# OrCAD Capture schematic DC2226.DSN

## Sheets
1 PAGE3: size B; title: WITH JESD204B SERIAL OUTPUTS; rev: 3; note: DEMO CIRCUIT 2226A
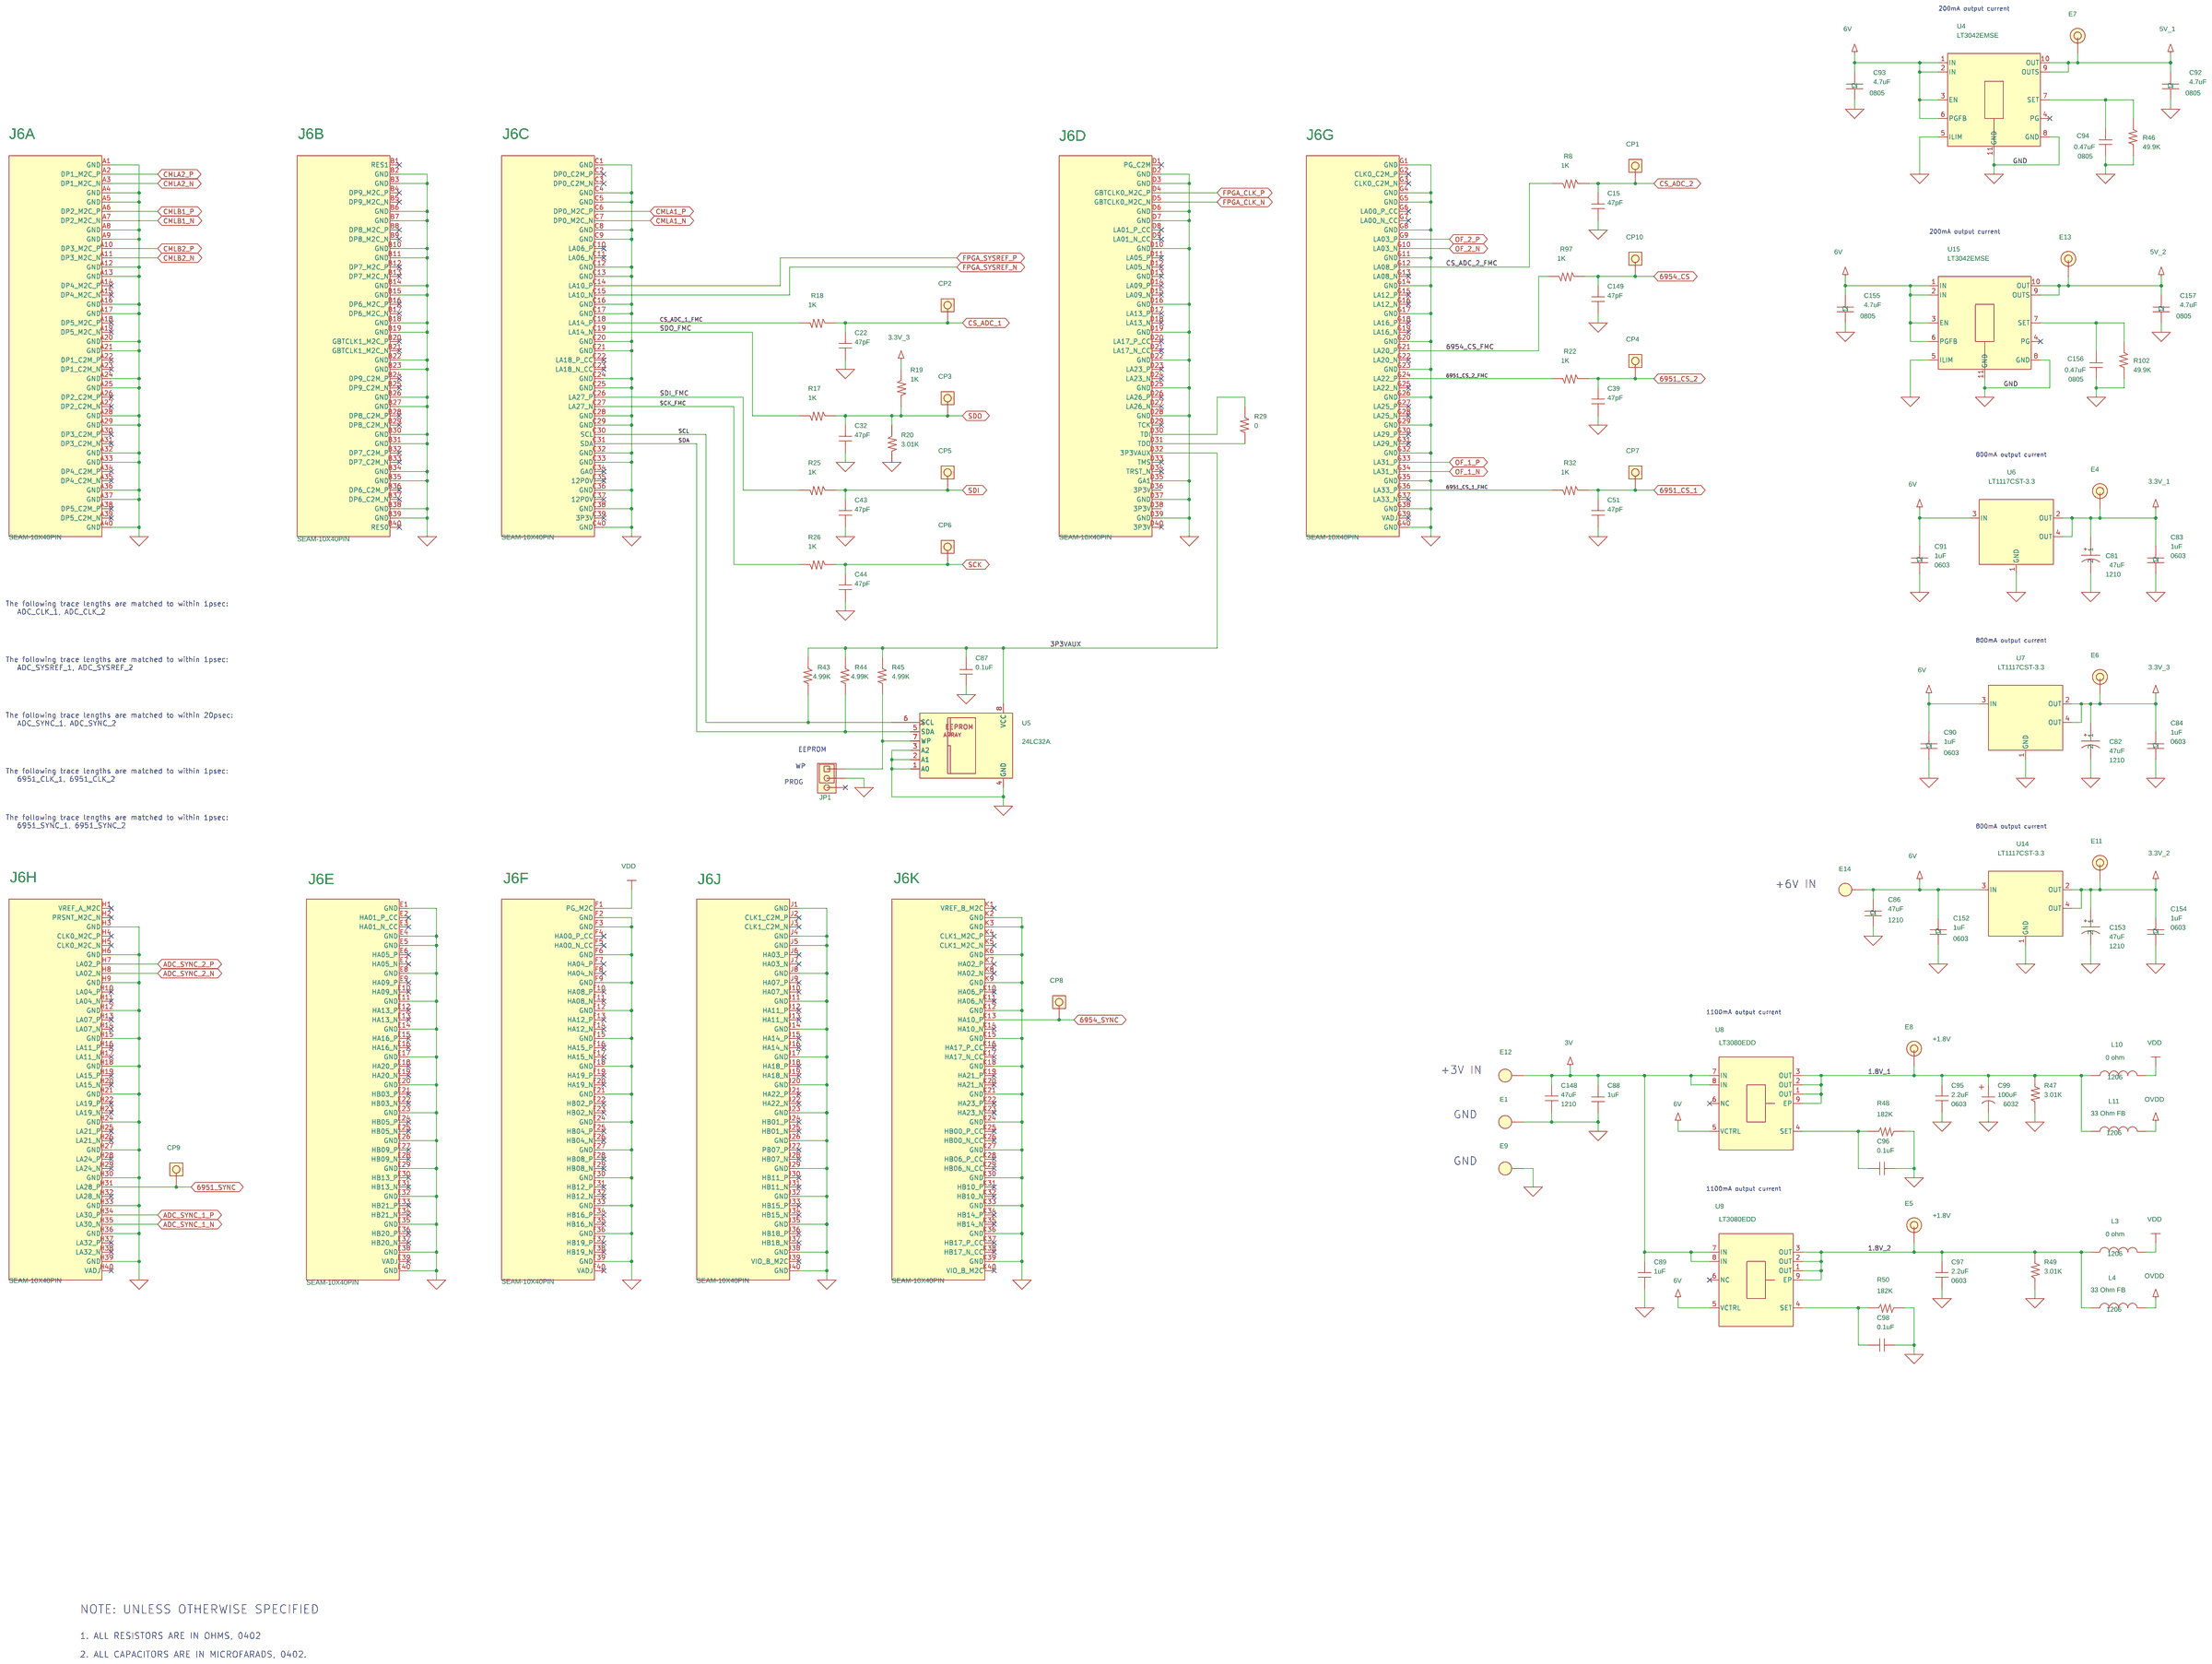
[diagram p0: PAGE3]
2 PAGE2: size B
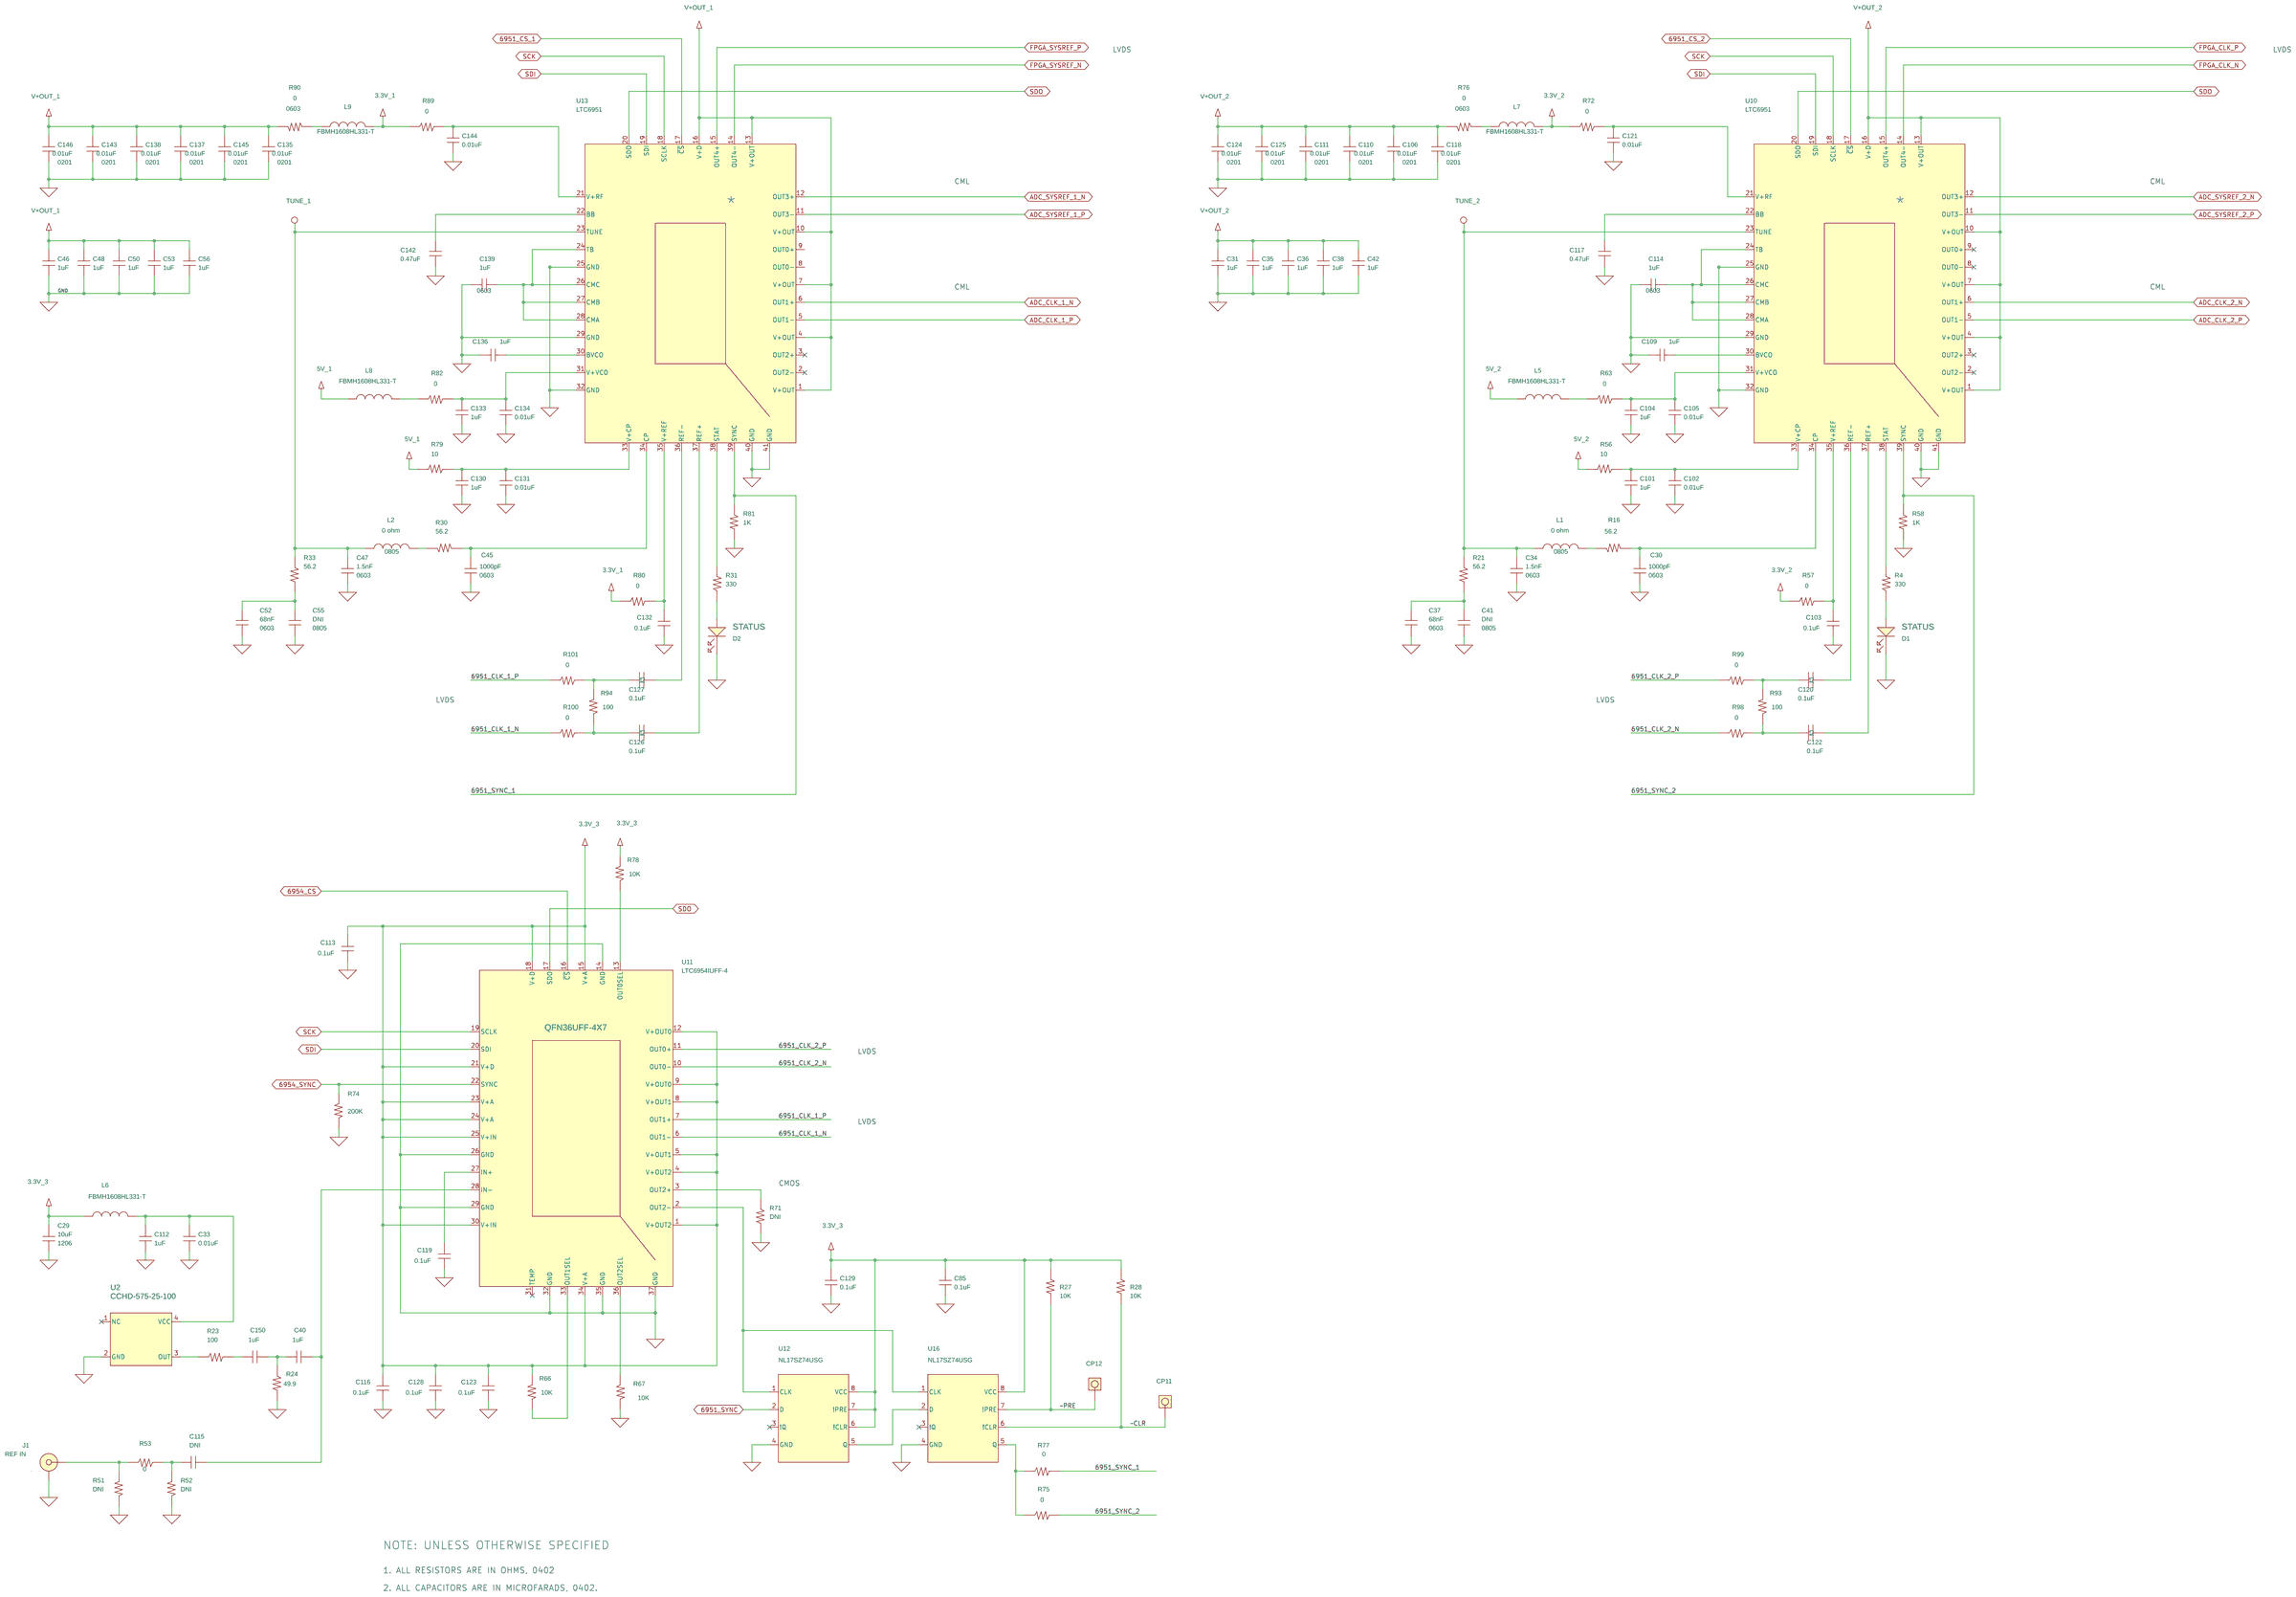
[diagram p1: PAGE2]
3 PAGE1: size B
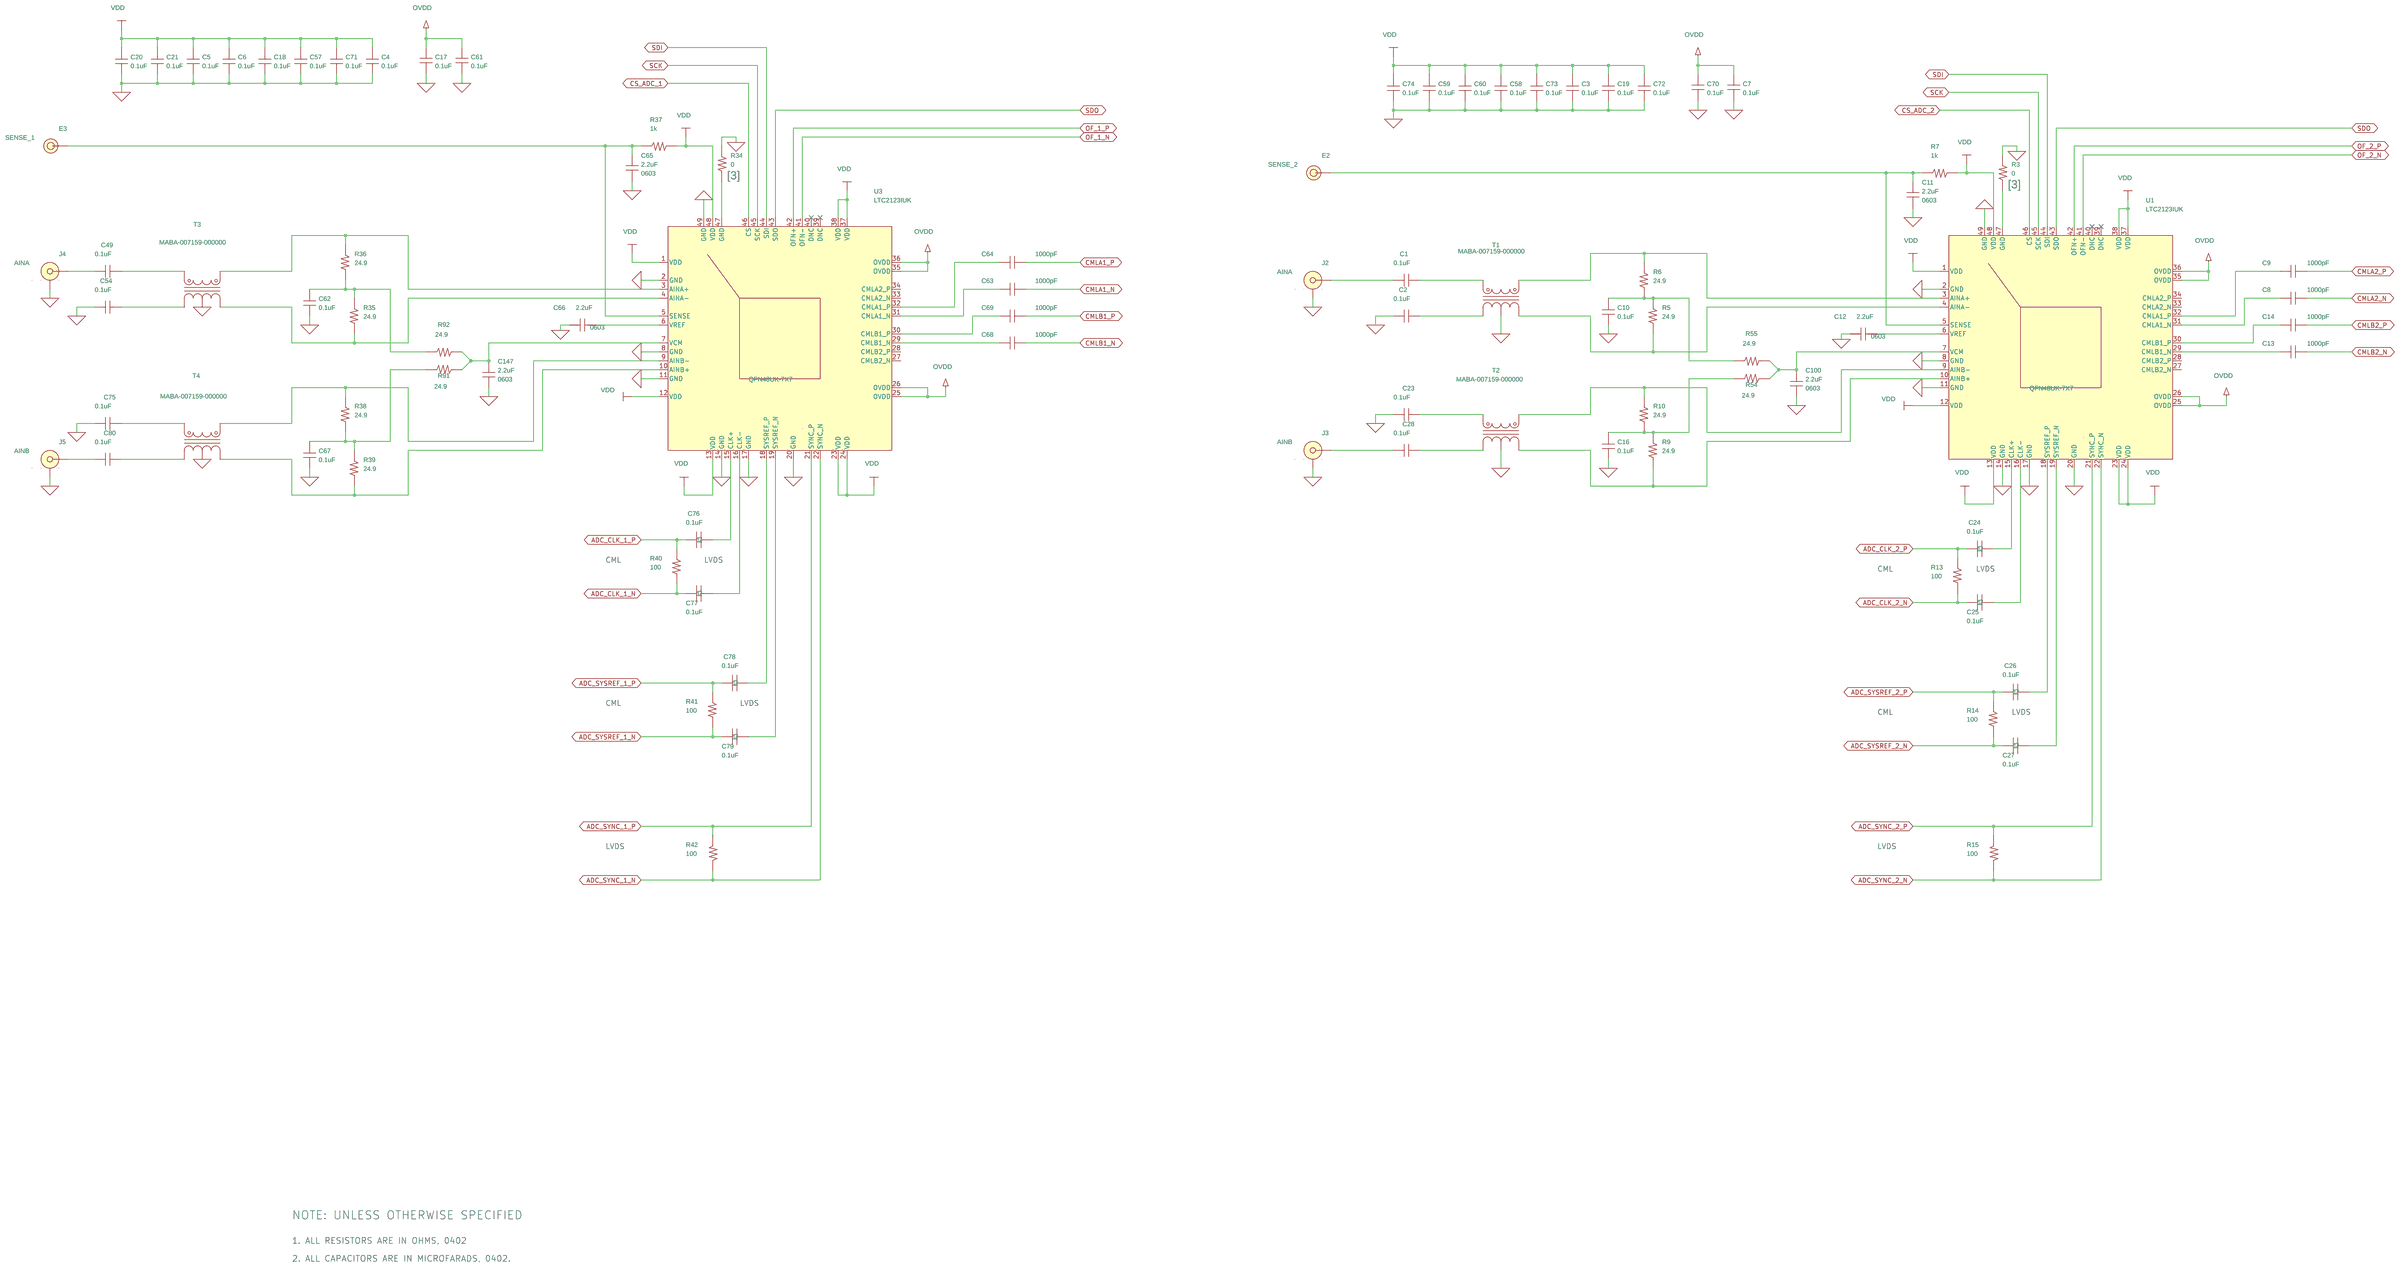
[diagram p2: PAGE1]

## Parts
sheet PAGE1
C1  0.1uF  [0402]
C2  0.1uF  [0402]
C3  0.1uF  [0402]
C4  0.1uF  [0402]
C5  0.1uF  [0402]
C6  0.1uF  [0402]
C7  0.1uF  [0402]
C8  1000pF  [0402]
C9  1000pF  [0402]
C10  0.1uF  [0402]
C11  2.2uF  [0603]
C12  2.2uF  [0603]
C13  1000pF  [0402]
C14  1000pF  [0402]
C16  0.1uF  [0402]
C17  0.1uF  [0402]
C18  0.1uF  [0402]
C19  0.1uF  [0402]
C20  0.1uF  [0402]
C21  0.1uF  [0402]
C23  0.1uF  [0402]
C24  0.1uF  [0402]
C25  0.1uF  [0402]
C26  0.1uF  [0402]
C27  0.1uF  [0402]
C28  0.1uF  [0402]
C49  0.1uF  [0402]
C54  0.1uF  [0402]
C57  0.1uF  [0402]
C58  0.1uF  [0402]
C59  0.1uF  [0402]
C60  0.1uF  [0402]
C61  0.1uF  [0402]
C62  0.1uF  [0402]
C63  1000pF  [0402]
C64  1000pF  [0402]
C65  2.2uF  [0603]
C66  2.2uF  [0603]
C67  0.1uF  [0402]
C68  1000pF  [0402]
C69  1000pF  [0402]
C70  0.1uF  [0402]
C71  0.1uF  [0402]
C72  0.1uF  [0402]
C73  0.1uF  [0402]
C74  0.1uF  [0402]
C75  0.1uF  [0402]
C76  0.1uF  [0402]
C77  0.1uF  [0402]
C78  0.1uF  [0402]
C79  0.1uF  [0402]
C80  0.1uF  [0402]
C100  2.2uF  [0603]
C147  2.2uF  [0603]
E2  MILL-MAX-2308  [MILL-MAX-2308]
E3  MILL-MAX-2308  [MILL-MAX-2308]
J2  CON-SMA-R-6LAYERS  [CON-SMA-R-6LAYERS]
J3  CON-SMA-R-6LAYERS  [CON-SMA-R-6LAYERS]
J4  CON-SMA-R-6LAYERS  [CON-SMA-R-6LAYERS]
J5  CON-SMA-R-6LAYERS  [CON-SMA-R-6LAYERS]
R3  0  [0402]
R5  24.9  [0402]
R6  24.9  [0402]
R7  1k  [0402]
R9  24.9  [0402]
R10  24.9  [0402]
R13  100  [0402]
R14  100  [0402]
R15  100  [0402]
R34  0  [0402]
R35  24.9  [0402]
R36  24.9  [0402]
R37  1k  [0402]
R38  24.9  [0402]
R39  24.9  [0402]
R40  100  [0402]
R41  100  [0402]
R42  100  [0402]
R54  24.9  [0402]
R55  24.9  [0402]
R91  24.9  [0402]
R92  24.9  [0402]
T1  MABA-007159-000000  [TRANS-SM-22-M/A-COM]
T2  MABA-007159-000000  [TRANS-SM-22-M/A-COM]
T3  MABA-007159-000000  [TRANS-SM-22-M/A-COM]
T4  MABA-007159-000000  [TRANS-SM-22-M/A-COM]
U1  LTC2123IUK  [QFN48UK-7X7]
U3  LTC2123IUK  [QFN48UK-7X7]
sheet PAGE2
C29  10uF  [1206]
C30  1000pF  [0603]
C31  1uF  [0402]
C33  0.01uF  [0402]
C34  1.5nF  [0603]
C35  1uF  [0402]
C36  1uF  [0402]
C37  68nF  [0603]
C38  1uF  [0402]
C40  1uF  [0402]
C41  DNI  [0805]
C42  1uF  [0402]
C45  1000pF  [0603]
C46  1uF  [0402]
C47  1.5nF  [0603]
C48  1uF  [0402]
C50  1uF  [0402]
C52  68nF  [0603]
C53  1uF  [0402]
C55  DNI  [0805]
C56  1uF  [0402]
C85  0.1uF  [0402]
C101  1uF  [0402]
C102  0.01uF  [0402]
C103  0.1uF  [0402]
C104  1uF  [0402]
C105  0.01uF  [0402]
C106  0.01uF  [0201]
C109  1uF  [0402]
C110  0.01uF  [0201]
C111  0.01uF  [0201]
C112  1uF  [0402]
C113  0.1uF  [0402]
C114  1uF  [0603]
C115  DNI  [0402]
C116  0.1uF  [0402]
C117  0.47uF  [0402]
C118  0.01uF  [0201]
C119  0.1uF  [0402]
C120  0.1uF  [0402]
C121  0.01uF  [0402]
C122  0.1uF  [0402]
C123  0.1uF  [0402]
C124  0.01uF  [0201]
C125  0.01uF  [0201]
C126  0.1uF  [0402]
C127  0.1uF  [0402]
C128  0.1uF  [0402]
C129  0.1uF  [0402]
C130  1uF  [0402]
C131  0.01uF  [0402]
C132  0.1uF  [0402]
C133  1uF  [0402]
C134  0.01uF  [0402]
C135  0.01uF  [0201]
C136  1uF  [0402]
C137  0.01uF  [0201]
C138  0.01uF  [0201]
C139  1uF  [0603]
C142  0.47uF  [0402]
C143  0.01uF  [0201]
C144  0.01uF  [0402]
C145  0.01uF  [0201]
C146  0.01uF  [0201]
C150  1uF  [0402]
CP11  TESTPAD-SMD/050SQ  [TESTPAD-SMD/050SQ]
CP12  TESTPAD-SMD/050SQ  [TESTPAD-SMD/050SQ]
D1  SML-010VT  [LED-ROHM-SML-010]
D2  SML-010VT  [LED-ROHM-SML-010]
J1  CON-SMA-R-6LAYERS  [AMPHENOL-132134]
L1  0 ohm  [0805]
L2  0 ohm  [0805]
L5  FBMH1608HL331-T  [L-0603LS-1608]
L6  FBMH1608HL331-T  [L-0603LS-1608]
L7  FBMH1608HL331-T  [L-0603LS-1608]
L8  FBMH1608HL331-T  [L-0603LS-1608]
L9  FBMH1608HL331-T  [L-0603LS-1608]
R4  330  [0402]
R16  56.2  [0402]
R21  56.2  [0402]
R23  100  [0402]
R24  49.9  [0402]
R27  10K  [0402]
R28  10K  [0402]
R30  56.2  [0402]
R31  330  [0402]
R33  56.2  [0402]
R51  DNI  [0402]
R52  DNI  [0402]
R53  0  [0402]
R56  10  [0402]
R57  0  [0402]
R58  1K  [0402]
R63  0  [0402]
R66  10K  [0402]
R67  10K  [0402]
R71  DNI  [0402]
R72  0  [0402]
R74  200K  [0402]
R75  0  [0402]
R76  0  [0603]
R77  0  [0402]
R78  10K  [0402]
R79  10  [0402]
R80  0  [0402]
R81  1K  [0402]
R82  0  [0402]
R89  0  [0402]
R90  0  [0603]
R93  100  [0402]
R94  100  [0402]
R98  0  [0402]
R99  0  [0402]
R100  0  [0402]
R101  0  [0402]
TUNE_1  TESTPAD-SMD/050SQ  [TESTPAD-SMD/050SQ]
TUNE_2  TESTPAD-SMD/050SQ  [TESTPAD-SMD/050SQ]
U2  CCHD-575-25-100  [CCHD575]
U10  LTC6951  [QFN40UHF-5X7]
U11  LTC6954IUFF-4  [QFN36UFF-4X7]
U12  NL17SZ74USG  [US8]
U13  LTC6951  [QFN40UHF-5X7]
U16  NL17SZ74USG  [US8]
sheet PAGE3
C15  47pF  [0402]
C22  47pF  [0402]
C32  47pF  [0402]
C39  47pF  [0402]
C43  47pF  [0402]
C44  47pF  [0402]
C51  47pF  [0402]
C81  47uF  [1210]
C82  47uF  [1210]
C83  1uF  [0603]
C84  1uF  [0603]
C86  47uF  [1210]
C87  0.1uF  [0402]
C88  1uF  [0402]
C89  1uF  [0402]
C90  1uF  [0603]
C91  1uF  [0603]
C92  4.7uF  [0805]
C93  4.7uF  [0805]
C94  0.47uF  [0805]
C95  2.2uF  [0603]
C96  0.1uF  [0402]
C97  2.2uF  [0603]
C98  0.1uF  [0402]
C99  100uF  [6032]
C148  47uF  [1210]
C149  47pF  [0402]
C152  1uF  [0603]
C153  47uF  [1210]
C154  1uF  [0603]
C155  4.7uF  [0805]
C156  0.47uF  [0805]
C157  4.7uF  [0805]
CP1  TESTPAD-SMD/050SQ  [TESTPAD-SMD/050SQ]
CP2  TESTPAD-SMD/050SQ  [TESTPAD-SMD/050SQ]
CP3  TESTPAD-SMD/050SQ  [TESTPAD-SMD/050SQ]
CP4  TESTPAD-SMD/050SQ  [TESTPAD-SMD/050SQ]
CP5  TESTPAD-SMD/050SQ  [TESTPAD-SMD/050SQ]
CP6  TESTPAD-SMD/050SQ  [TESTPAD-SMD/050SQ]
CP7  TESTPAD-SMD/050SQ  [TESTPAD-SMD/050SQ]
CP8  TESTPAD-SMD/050SQ  [TESTPAD-SMD/050SQ]
CP9  TESTPAD-SMD/050SQ  [TESTPAD-SMD/050SQ]
CP10  TESTPAD-SMD/050SQ  [TESTPAD-SMD/050SQ]
E1  MILL-MAX-2501  [MILL-MAX-2501]
E4  MILL-MAX-2308  [MILL-MAX-2308]
E5  MILL-MAX-2308  [MILL-MAX-2308]
E6  MILL-MAX-2308  [MILL-MAX-2308]
E7  MILL-MAX-2308  [MILL-MAX-2308]
E8  MILL-MAX-2308  [MILL-MAX-2308]
E9  MILL-MAX-2501  [MILL-MAX-2501]
E11  MILL-MAX-2308  [MILL-MAX-2308]
E12  MILL-MAX-2501  [MILL-MAX-2501]
E13  MILL-MAX-2308  [MILL-MAX-2308]
E14  MIL-MAX-2501  [MILL-MAX-2501]
J6  SEAM-10X40PIN  [CON-SEAM-10X40PIN]  (sections A,B,C,D,E,F,G,H,J,K)
JP1  HD1X3-079  [HD1X3-079]
L3  0 ohm  [1206]
L4  33 Ohm FB  [1206]
L10  0 ohm  [1206]
L11  33 Ohm FB  [1206]
R8  1K  [0402]
R17  1K  [0402]
R18  1K  [0402]
R19  1K  [0402]
R20  3.01K  [0402]
R22  1K  [0402]
R25  1K  [0402]
R26  1K  [0402]
R29  0  [0402]
R32  1K  [0402]
R43  4.99K  [0402]
R44  4.99K  [0402]
R45  4.99K  [0402]
R46  49.9K  [0402]
R47  3.01K  [0402]
R48  182K  [0402]
R49  3.01K  [0402]
R50  182K  [0402]
R97  1K  [0402]
R102  49.9K  [0402]
U4  LT3042EMSE  [MSOP10]
U5  24LC32A  [TSSOP8]
U6  LT1117CST-3.3  [SOT223]
U7  LT1117CST-3.3  [SOT223]
U8  LT3080EDD  [DFN8DD]
U9  LT3080EDD  [DFN8DD]
U14  LT1117CST-3.3  [SOT223]
U15  LT3042EMSE  [MSOP10]

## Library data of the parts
C1-C23 C28 C32 C37 C39 C40 C43 C44 C49 C51 C52 C54 C57-C75 C80 C85 C87-C89 C95-C98 C100 C129 C147-C150 = CAP-NP
C24 C127 = CAP_NP_3: 1st Part Field: 50V; 5th Part Field: 12065C104KATM; 7th Part Field: CAP.,
C25 = CAP_NP_7: 1st Part Field: 50V; 5th Part Field: 12065C104KATM; 7th Part Field: CAP.,
C26 C122 = CAP_NP: 1st Part Field: 50V; 5th Part Field: 12065C104KATM; 7th Part Field: CAP.,
C27 = CAP_NP_4: 1st Part Field: 50V; 5th Part Field: 12065C104KATM; 7th Part Field: CAP.,
C76 = CAP_NP_6: 1st Part Field: 50V; 5th Part Field: 12065C104KATM; 7th Part Field: CAP.,
C77 = CAP_NP_5: 1st Part Field: 50V; 5th Part Field: 12065C104KATM; 7th Part Field: CAP.,
C78 C120 = CAP_NP_1: 1st Part Field: 50V; 5th Part Field: 12065C104KATM; 7th Part Field: CAP.,
C79 C126 = CAP_NP_2: 1st Part Field: 50V; 5th Part Field: 12065C104KATM; 7th Part Field: CAP.,
E2 = E_1: STATUS: 1.6V, 1.8V, 2.0V OR 2.5V @ 15A; label: SENSE_2
E3 = E_1: STATUS: 1.6V, 1.8V, 2.0V OR 2.5V @ 15A; label: SENSE_1
J2 J4 = CON_SMA-END_3: CONN, BNC, SMA 50-OHM EDGE-LANCH; Part Number: E.F.JOHNSON, 142-0701-851; label: AINA
J3 J5 = CON_SMA-END_3: CONN, BNC, SMA 50-OHM EDGE-LANCH; Part Number: E.F.JOHNSON, 142-0701-851; label: AINB
R3 R34 = R: 1st Part Field: [3]
R4-R10 R13-R15 R17-R29 R31-R33 R35-R50 R53-R58 R63 R71 R72 R74-R77 R79-R82 R89-R92 R97-R102 = R
T1-T4 = TRANS-MABA-007159
U1 U3 = LTC212XIUK-QFN48UK-7X7
C29 = CAP-NP: 2nd Part Field: 10%; 4th Part Field: TDK; 5th Part Field: C2012X7R1C105K
C30 C45 = CAP-NP: CAP, 0603 TBD; 1st Part Field: 50V; 5th Part Field: 12065C104KATM; 7th Part Field: CAP.,; Part Number: TBD
C31 C33 C35 C36 C38 C42 C46 C48 C50 C53 C56 C94 C101-C106 C109-C113 C116-C119 C121 C123-C125 C128 C130-C138 C142-C146 C156 = CAP-NP: 1st Part Field: 50V; 5th Part Field: 12065C104KATM; 7th Part Field: CAP.,
C34 C41 C47 C55 = CAP-NP: 1st Part Field: 50V
C114 C139 = CAP-NP: CAP, 0603 TBD; 1st Part Field: 50V; 2nd Part Field: 10%; 5th Part Field: 12065C104KATM; 7th Part Field: CAP.,; Part Number: TBD
C115 = CAP-NP: 1st Part Field: 50V; 2nd Part Field: 10%; 5th Part Field: 12065C104KATM; 7th Part Field: CAP.,; OPT: OPT
CP1-CP12 = E_4: STATUS: 1.6V, 1.8V, 2.0V OR 2.5V @ 15A; label: CP
D1 D2 = LED-ROHM-SML-010VT-RED: PART FIELD 1: STATUS
J1 = CON_SMA-END_3: CONN, BNC, SMA 50-OHM EDGE-LANCH; Part Number: E.F.JOHNSON, 142-0701-851; label: REF IN
L1 L2 L5-L9 = IND: IND, 0805 TBD; COMPFIXED: CDR6D28MNNP-7R7NC; COMPGROUP: SUMIDA; Part Number: TBD
R16 R30 = R: RES, 0603 TBD; 1st Part Field: 1/8W; 5th Part Field: 9C12063A51R0JM; 7th Part Field: RES.,; Part Number: TBD
R51 R52 R66 R67 R78 R93 R94 = R: OPT: OPT
TUNE_1 TUNE_2 = E-060-035
U2 = XXXXX4_0: 1: OPT
U10 U13 = LTC6951IUHF-QFN40UHF-5X7
U11 = LTC6954EUFF-QFN36UFF-4X7_0: 1st Part Field: *
U12 U16 = SN74LVC2G00DCU-US8_0
C81 = tant_1: 16V: 20V
C82 = tant: 16V: 20V
C83 = CAP_NP: 7th Part Field: CAP.,
C84 = CAP_NP_8: 7th Part Field: CAP.,
C86 = CAP_NP_9: 7th Part Field: CAP.,
C90 = CAP_NP_1: 7th Part Field: CAP.,
C91 = CAP_NP_7: 7th Part Field: CAP.,
C92 = CAP_NP_10: 7th Part Field: CAP.,
C93 = CAP_NP_2: 7th Part Field: CAP.,
C99 = CAP: 1st Part Field: 10V
C152 = CAP_NP_5: 7th Part Field: CAP.,
C153 = tant_2: 16V: 20V
C154 = CAP_NP_6: 7th Part Field: CAP.,
C155 = CAP_NP_4: 7th Part Field: CAP.,
C157 = CAP_NP_3: 7th Part Field: CAP.,
E1 E9 E12 E14 = E-094
E4-E8 E11 E13 = E_1: STATUS: 1.6V, 1.8V, 2.0V OR 2.5V @ 15A; label: +1.8V
J6 = CON-SAMTEC-SEAM40-10X40
JP1 = HD1X3: HEADER, 3 PIN, .079
L3 L4 L10 L11 = IND: FERRITE BEAD, 1206; Part Number: MURATA BLM31PG330SN1L
U4 U15 = LT3080EDD-DFN8DD_1
U5 = 24LC032-I_ST
U6 U7 U14 = LT1965T_0
U8 U9 = LT3080EDD-DFN8DD

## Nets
1.8V_1: C95.1 C99.1 E8.1(A) L10.1 L11.1 R47.2 U8.1(OUT) U8.2(OUT) U8.3(OUT) U8.9(EP)
1.8V_2: C97.1 E5.1(A) L3.1 L4.1 R49.2 U9.1(OUT) U9.2(OUT) U9.3(OUT) U9.9(EP)
3.3V_1: C81.1 C83.2 E4.1(A) L9.1 R80.1 R89.1 U6.2(OUT) U6.4(OUT)
3.3V_2: C153.1 C154.2 E11.1(A) L7.1 R57.1 R72.1 U14.2(OUT) U14.4(OUT)
3.3V_3: C29.2 C82.1 C84.2 C85.2 C113.2 C116.2 C123.2 C128.2 C129.2 E6.1(A) L6.1 R19.1 R27.1 R28.1 R66.2 R78.2 U7.2(OUT) U7.4(OUT) U11.1(V+OUT2) U11.4(V+OUT2) U11.5(V+OUT1) U11.8(V+OUT1) U11.9(V+OUT0) U11.12(V+OUT0) U11.15(V+A) U11.18(V+D) U11.21(V+D) U11.23(V+A) U11.24(V+A) U11.25(V+IN) U11.30(V+IN) U11.34(V+A) U12.6(!CLR) U12.7(!PRE) U12.8(VCC) U16.8(VCC)
3V: C88.2 C89.1 C148.1 E12.1(A) U8.7(IN) U8.8(IN) U9.7(IN) U9.8(IN)
5V_1: C92.2 E7.1(A) L8.1 R79.2 U4.9(OUTS) U4.10(OUT)
5V_2: C157.2 E13.1(A) L5.1 R56.2 U15.9(OUTS) U15.10(OUT)
6V: C86.2 C90.2 C91.2 C93.2 C152.2 C155.2 E14.1(A) U4.1(IN) U4.2(IN) U4.3(EN) U4.6(PGFB) U6.3(IN) U7.3(IN) U8.5(VCTRL) U9.5(VCTRL) U14.3(IN) U15.1(IN) U15.2(IN) U15.3(EN) U15.6(PGFB)
GND: C2.1 C3.1 C4.1 C5.1 C6.1 C7.2 C10.1 C11.2 C12.1 C15.2 C16.1 C17.2 C18.1 C19.1 C20.1 C21.1 C22.2 C23.1 C29.1 C30.1 C31.1 C32.2 C33.1 C34.1 C35.1 C36.1 C37.2 C38.1 C39.2 C41.2 C42.1 C43.2 C44.2 C45.1 C46.1 C47.1 C48.1 C50.1 C51.2 C52.2 C53.1 C54.1 C55.2 C56.1 C57.1 C58.1 C59.1 C60.1 C61.2 C62.1 C65.2 C66.1 C67.1 C70.2 C71.1 C72.1 C73.1 C74.1 C75.1 C81.2 C82.2 C83.1 C84.1 C85.1 C86.1 C87.1 C88.1 C89.2 C90.1 C91.1 C92.1 C93.1 C94.1 C95.2 C96.1 C97.2 C98.1 C99.2 C100.1 C101.1 C102.1 C103.1 C104.1 C105.1 C106.1 C109.2 C110.1 C111.1 C112.1 C113.1 C114.2 C116.1 C117.2 C118.1 C119.1 C121.1 C123.1 C124.1 C125.1 C128.1 C129.1 C130.1 C131.1 C132.1 C133.1 C134.1 C135.1 C136.2 C137.1 C138.1 C139.2 C142.2 C143.1 C144.1 C145.1 C146.1 C147.1 C148.2 C149.2 C152.1 C153.2 C154.1 C155.1 C156.1 C157.1 D1.2 D2.2 E1.1(A) E9.1(A) J1.2(SGND) J1.3(SGND) J1.4(GND) J1.5(SGND) J2.2(SGND) J2.3(SGND) J2.4(GND) J2.5(SGND) J3.2(SGND) J3.3(SGND) J3.4(GND) J3.5(SGND) J4.2(SGND) J4.3(SGND) J4.4(GND) J4.5(SGND) J5.2(SGND) J5.3(SGND) J5.4(GND) J5.5(SGND) J6.A1(GND) J6.A4(GND) J6.A5(GND) J6.A8(GND) J6.A9(GND) J6.A12(GND) J6.A13(GND) J6.A16(GND) J6.A17(GND) J6.A20(GND) J6.A21(GND) J6.A24(GND) J6.A25(GND) J6.A28(GND) J6.A29(GND) J6.A32(GND) J6.A33(GND) J6.A36(GND) J6.A37(GND) J6.A40(GND) J6.B2(GND) J6.B3(GND) J6.B6(GND) J6.B7(GND) J6.B10(GND) J6.B11(GND) J6.B14(GND) J6.B15(GND) J6.B18(GND) J6.B19(GND) J6.B22(GND) J6.B23(GND) J6.B26(GND) J6.B27(GND) J6.B30(GND) J6.B31(GND) J6.B34(GND) J6.B35(GND) J6.B38(GND) J6.B39(GND) J6.C1(GND) J6.C4(GND) J6.C5(GND) J6.C8(GND) J6.C9(GND) J6.C12(GND) J6.C13(GND) J6.C16(GND) J6.C17(GND) J6.C20(GND) J6.C21(GND) J6.C24(GND) J6.C25(GND) J6.C28(GND) J6.C29(GND) J6.C32(GND) J6.C33(GND) J6.C36(GND) J6.C38(GND) J6.C40(GND) J6.D2(GND) J6.D3(GND) J6.D6(GND) J6.D7(GND) J6.D10(GND) J6.D16(GND) J6.D19(GND) J6.D22(GND) J6.D25(GND) J6.D28(GND) J6.D35(GA1) J6.D37(GND) J6.D39(GND) J6.E1(GND) J6.E4(GND) J6.E5(GND) J6.E8(GND) J6.E11(GND) J6.E14(GND) J6.E17(GND) J6.E20(GND) J6.E23(GND) J6.E26(GND) J6.E29(GND) J6.E32(GND) J6.E35(GND) J6.E38(GND) J6.E40(GND) J6.F2(GND) J6.F3(GND) J6.F6(GND) J6.F9(GND) J6.F12(GND) J6.F15(GND) J6.F18(GND) J6.F21(GND) J6.F24(GND) J6.F27(GND) J6.F30(GND) J6.F33(GND) J6.F36(GND) J6.F39(GND) J6.G1(GND) J6.G4(GND) J6.G5(GND) J6.G8(GND) J6.G11(GND) J6.G14(GND) J6.G17(GND) J6.G20(GND) J6.G23(GND) J6.G26(GND) J6.G29(GND) J6.G32(GND) J6.G35(GND) J6.G38(GND) J6.G40(GND) J6.H3(GND) J6.H6(GND) J6.H9(GND) J6.H12(GND) J6.H15(GND) J6.H18(GND) J6.H21(GND) J6.H24(GND) J6.H27(GND) J6.H30(GND) J6.H33(GND) J6.H36(GND) J6.H39(GND) J6.J1(GND) J6.J4(GND) J6.J5(GND) J6.J8(GND) J6.J11(GND) J6.J14(GND) J6.J17(GND) J6.J20(GND) J6.J23(GND) J6.J26(GND) J6.J29(GND) J6.J32(GND) J6.J35(GND) J6.J38(GND) J6.J40(GND) J6.K2(GND) J6.K3(GND) J6.K6(GND) J6.K9(GND) J6.K12(GND) J6.K15(GND) J6.K18(GND) J6.K21(GND) J6.K24(GND) J6.K27(GND) J6.K30(GND) J6.K33(GND) J6.K36(GND) J6.K39(GND) JP1.2 R3.2 R20.2 R24.2 R34.2 R46.2 R47.1 R48.2 R49.1 R50.2 R51.1 R52.1 R58.2 R67.2 R71.2 R74.1 R81.2 R102.2 T1.2 T2.2 T3.2 T4.2 U1.2(GND) U1.8(GND) U1.11(GND) U1.14(GND) U1.17(GND) U1.20(GND) U1.49(GND) U2.2(GND) U3.2(GND) U3.8(GND) U3.11(GND) U3.14(GND) U3.17(GND) U3.20(GND) U3.49(GND) U4.5(ILIM) U4.8(GND) U4.11(GND) U5.1(A0) U5.2(A1) U5.3(A2) U5.4(GND) U6.1(GND) U7.1(GND) U10.25(GND) U10.29(GND) U10.32(GND) U10.40(GND) U10.41(GND) U11.14(GND) U11.26(GND) U11.29(GND) U11.32(GND) U11.35(GND) U11.37(GND) U12.4(GND) U13.25(GND) U13.29(GND) U13.32(GND) U13.40(GND) U13.41(GND) U14.1(GND) U15.5(ILIM) U15.8(GND) U15.11(GND) U16.4(GND)
VDD: C3.2 C4.2 C5.2 C6.2 C18.2 C19.2 C20.2 C21.2 C57.2 C58.2 C59.2 C60.2 C71.2 C72.2 C73.2 C74.2 J6.F1(PG_M2C) L3.2 L10.2 R7.2 R37.2 U1.1(VDD) U1.12(VDD) U1.13(VDD) U1.23(VDD) U1.24(VDD) U1.37(VDD) U1.38(VDD) U1.48(VDD) U3.1(VDD) U3.12(VDD) U3.13(VDD) U3.23(VDD) U3.24(VDD) U3.37(VDD) U3.38(VDD) U3.48(VDD)
3P3VAUX: C87.2 J6.D32(3P3VAUX) R43.1 R44.1 R45.1 U5.8(VCC)
6951_CLK_1_N: R100.1 U11.6(OUT1-)
6951_CLK_1_P: R101.1 U11.7(OUT1+)
6951_CLK_2_N: R98.1 U11.10(OUT0-)
6951_CLK_2_P: R99.1 U11.11(OUT0+)
6951_CS_1: C51.1 CP7.1(A) R32.1 U13.17(~{CS})
6951_CS_1_FMC: J6.G36(LA33_P) R32.2
6951_CS_2: C39.1 CP4.1(A) R22.1 U10.17(~{CS})
6951_CS_2_FMC: J6.G24(LA22_P) R22.2
6951_SYNC: CP9.1(A) J6.H31(LA28_P) U12.2(D)
6951_SYNC_1: R77.2 R81.1 U13.39(SYNC)
6951_SYNC_2: R58.1 R75.2 U10.39(SYNC)
6954_CS: C149.1 CP10.1(A) R97.1 U11.16(~{CS})
6954_CS_FMC: J6.G21(LA20_P) R97.2
6954_SYNC: CP8.1(A) J6.K13(HA10_P) R74.2 U11.22(SYNC)
ADC_CLK_1_N: C77.1 R40.2 U13.6(OUT1+)
ADC_CLK_1_P: C76.1 R40.1 U13.5(OUT1-)
ADC_CLK_2_N: C25.1 R13.2 U10.6(OUT1+)
ADC_CLK_2_P: C24.1 R13.1 U10.5(OUT1-)
ADC_SYNC_1_N: J6.H35(LA30_N) R42.2 U3.22(SYNC_N)
ADC_SYNC_1_P: J6.H34(LA30_P) R42.1 U3.21(SYNC_P)
ADC_SYNC_2_N: J6.H8(LA02_N) R15.2 U1.22(SYNC_N)
ADC_SYNC_2_P: J6.H7(LA02_P) R15.1 U1.21(SYNC_P)
ADC_SYSREF_1_N: C79.1 R41.2 U13.12(OUT3+)
ADC_SYSREF_1_P: C78.1 R41.1 U13.11(OUT3-)
ADC_SYSREF_2_N: C27.1 R14.2 U10.12(OUT3+)
ADC_SYSREF_2_P: C26.1 R14.1 U10.11(OUT3-)
CMLA1_N: C63.2 J6.C7(DP0_M2C_N)
CMLA1_P: C64.2 J6.C6(DP0_M2C_P)
CMLA2_N: C8.2 J6.A3(DP1_M2C_N)
CMLA2_P: C9.2 J6.A2(DP1_M2C_P)
CMLB1_N: C68.2 J6.A7(DP2_M2C_N)
CMLB1_P: C69.2 J6.A6(DP2_M2C_P)
CMLB2_N: C13.2 J6.A11(DP3_M2C_N)
CMLB2_P: C14.2 J6.A10(DP3_M2C_P)
CS_ADC_1: C22.1 CP2.1(A) R18.1 U3.46(CS)
CS_ADC_1_FMC: J6.C18(LA14_P) R18.2
CS_ADC_2: C15.1 CP1.1(A) R8.1 U1.46(CS)
CS_ADC_2_FMC: J6.G12(LA08_P) R8.2
FPGA_CLK_N: J6.D5(GBTCLK0_M2C_N) U10.14(OUT4-)
FPGA_CLK_P: J6.D4(GBTCLK0_M2C_P) U10.15(OUT4+)
FPGA_SYSREF_N: J6.C15(LA10_N) U13.14(OUT4-)
FPGA_SYSREF_P: J6.C14(LA10_P) U13.15(OUT4+)
OF_1_N: J6.G34(LA31_N) U3.41(OFN-)
OF_1_P: J6.G33(LA31_P) U3.42(OFN+)
OF_2_N: J6.G10(LA03_N) U1.41(OFN-)
OF_2_P: J6.G9(LA03_P) U1.42(OFN+)
OVDD: C7.1 C17.1 C61.1 C70.1 L4.2 L11.2 U1.25(OVDD) U1.26(OVDD) U1.35(OVDD) U1.36(OVDD) U3.25(OVDD) U3.26(OVDD) U3.35(OVDD) U3.36(OVDD)
SCK: C44.1 CP6.1(A) R26.1 U1.45(SCK) U3.45(SCK) U10.18(SCLK) U11.19(SCLK) U13.18(SCLK)
SCK_FMC: J6.C27(LA27_N) R26.2
SCL: J6.C30(SCL) R43.2 U5.6(SCL)
SDA: J6.C31(SDA) R44.2 U5.5(SDA)
SDI: C43.1 CP5.1(A) R25.1 U1.44(SDI) U3.44(SDI) U10.19(SDI) U11.20(SDI) U13.19(SDI)
SDI_FMC: J6.C26(LA27_P) R25.2
SDO: C32.1 CP3.1(A) R17.1 R19.2 R20.1 U1.43(SDO) U3.43(SDO) U10.20(SDO) U11.17(SDO) U13.20(SDO)
SDO_FMC: J6.C19(LA14_N) R17.2
V+OUT_1: C46.2 C48.2 C50.2 C53.2 C56.2 C135.2 C137.2 C138.2 C143.2 C145.2 C146.2 R90.2 U13.1(V+OUT) U13.4(V+OUT) U13.7(V+OUT) U13.10(V+OUT) U13.13(V+OUT) U13.16(V+D)
V+OUT_2: C31.2 C35.2 C36.2 C38.2 C42.2 C106.2 C110.2 C111.2 C118.2 C124.2 C125.2 R76.2 U10.1(V+OUT) U10.4(V+OUT) U10.7(V+OUT) U10.10(V+OUT) U10.13(V+OUT) U10.16(V+D)
~CLR: CP11.1(A) R28.2 U16.6(!CLR)
~PRE: CP12.1(A) R27.2 U16.7(!PRE)
N11826: R36.1 T3.1 U3.3(AINA+)
N11872: R35.2 T3.3 U3.4(AINA-)
N304795: R66.1 U11.33(OUT1SEL)
N312924: U11.2(OUT2-) U12.1(CLK) U16.1(CLK)
N322218: R71.1 U11.3(OUT2+)
N894818: R67.1 U11.36(OUT2SEL)
N900460: R78.1 U11.13(OUT0SEL)
N16506318: C49.2 T3.5
N16653279: C65.1 E3.1(A) R37.1 U3.5(SENSE)
N16653535: C66.2 U3.6(VREF)
N16654825: R38.1 T4.1 U3.9(AINB-)
N16654975: R39.2 T4.3 U3.10(AINB+)
N16661419: C75.2 T4.5
N16661487: C80.1 J5.1(CENTER)
N16778390: C26.2 U1.18(SYSREF_P)
N16778813: C100.2 R54.1 R55.2 U1.7(VCM)
N16778933: R10.1 T2.1 U1.9(AINB-)
N16779344: C11.1 E2.1(A) R7.1 U1.5(SENSE)
N16779489: R6.1 T1.1 U1.3(AINA+)
N16779792: C10.2 R5.1 R6.2 R55.1
N16779794: C2.2 T1.4
N16780899: R9.2 T2.3 U1.10(AINB+)
N16781013: C16.2 R9.1 R10.2 R54.2
N16781067: R5.2 T1.3 U1.4(AINA-)
N16785930: C40.2 C115.2 U11.28(IN-)
N16786074: C28.1 J3.1(CENTER)
N16786211: C8.1 U1.31(CMLA1_N)
N16786470: C1.1 J2.1(CENTER)
N16786572: C27.2 U1.19(SYSREF_N)
N16786594: C9.1 U1.32(CMLA1_P)
N16786598: C1.2 T1.5
N16786746: C12.2 U1.6(VREF)
N16786795: R3.1 U1.47(GND)
N16787007: C13.1 U1.29(CMLB1_N)
N16787107: C14.1 U1.30(CMLB1_P)
N16788190: R75.1 R77.1 U16.5(Q)
N16788959: C96.2 R48.1 U8.4(SET)
N16789395: C98.2 R50.1 U9.4(SET)
N16797479: C120.1 R93.2 R99.2
N16797520: C122.1 R93.1 R98.2
N16797561: C127.1 R94.2 R101.2
N16797602: C126.1 R94.1 R100.2
N16798806: C33.2 C112.2 L6.2 U2.4(VCC)
N16799381: C40.1 C150.2 R24.1
N16799391: C150.1 R23.2
N16799658: C156.2 R102.1 U15.7(SET)
N16806262: C76.2 U3.15(CLK+)
N16806324: C77.2 U3.16(CLK-)
N16806395: C24.2 U1.15(CLK+)
N16806452: C25.2 U1.16(CLK-)
N16815624: C79.2 U3.19(SYSREF_N)
N16815628: C78.2 U3.18(SYSREF_P)
N16816775: C130.2 C131.2 R79.1 U13.33(V+CP)
N16816796: C132.2 R80.2 U13.35(V+REF)
N16816824: C133.2 C134.2 R82.2 U13.31(V+VCO)
N16816871: C45.2 R30.2 U13.34(CP)
N16816997: C139.1 U13.24(TB) U13.26(CMC) U13.27(CMB) U13.28(CMA)
N16817083: C47.2 L2.2 R33.1 TUNE_1.1 U13.23(TUNE)
N16817209: C52.1 C55.1 R33.2
N16817225: C115.1 R52.2 R53.2
N16817383: R23.1 U2.3(OUT)
N16817562: C144.2 R89.2 U13.21(V+RF)
N16817662: C142.1 U13.22(BB)
N16817782: R31.2 U13.38(STAT)
N16817817: L8.2 R82.1
N16817892: C136.1 U13.30(BVCO)
N16817991: L9.2 R90.1
N16818068: L2.1 R30.1
N16818316: J1.1(CENTER) R51.2 R53.1
N16818722: D2.1 R31.1
N16820259: C30.2 R16.2 U10.34(CP)
N16820263: C104.2 C105.2 R63.2 U10.31(V+VCO)
N16820686: C121.2 R72.2 U10.21(V+RF)
N16820698: R4.2 U10.38(STAT)
N16820804: C101.2 C102.2 R56.1 U10.33(V+CP)
N16820847: L5.2 R63.1
N16820902: C34.2 L1.2 R21.1 TUNE_2.1 U10.23(TUNE)
N16820906: C103.2 R57.2 U10.35(V+REF)
N16821492: D1.1 R4.1
N16821637: L1.1 R16.1
N16822222: L7.2 R76.1
N16851434: C37.1 C41.1 R21.2
N16859847: C94.2 R46.1 U4.7(SET)
N16871707: C63.1 U3.31(CMLA1_N)
N16871717: C64.1 U3.32(CMLA1_P)
N16871779: C69.1 U3.30(CMLB1_P)
N16871783: C68.1 U3.29(CMLB1_N)
N16882328: C114.1 U10.24(TB) U10.26(CMC) U10.27(CMB) U10.28(CMA)
N16882364: C117.1 U10.22(BB)
N16882449: C109.1 U10.30(BVCO)
N16915051: C126.2 U13.37(REF+)
N16915103: C127.2 U13.36(REF-)
N16915228: C120.2 U10.36(REF-)
N16915278: C122.2 U10.37(REF+)
N16915614: C119.2 U11.27(IN+)
N16934181: C62.2 R35.1 R36.2 R92.1
N16934952: C67.2 R38.2 R39.1 R91.2
N16944587: JP1.1 R45.2 U5.7(WP)
N16961935: U12.5(Q) U16.2(D)
N17029107: C23.2 T2.5
N17029124: C28.2 T2.4
N18007671: R34.1 U3.47(GND)
N18063227: C80.2 T4.4
N18898954: C49.1 J4.1(CENTER)
N18909235: C54.2 T3.4
N19104936: C147.2 R91.1 R92.2 U3.7(VCM)
N20839524: J6.D31(TDO) R29.2
N20840061: J6.D30(TDI) R29.1

Not connected (* = marked no-connect by the designer): J6 A14(DP4_M2C_P)* A15(DP4_M2C_N)* A18(DP5_M2C_P)* A19(DP5_M2C_N)* A22(DP1_C2M_P)* A23(DP1_C2M_N)* A26(DP2_C2M_P)* A27(DP2_C2M_N)* A30(DP3_C2M_P)* A31(DP3_C2M_N)* A34(DP4_C2M_P)* A35(DP4_C2M_N)* A38(DP5_C2M_P)* A39(DP5_C2M_N)* B1(RES1)* B4(DP9_M2C_P)* B5(DP9_M2C_N)* B8(DP8_M2C_P)* B9(DP8_M2C_N)* B12(DP7_M2C_P)* B13(DP7_M2C_N)* B16(DP6_M2C_P)* B17(DP6_M2C_N)* B20(GBTCLK1_M2C_P)* B21(GBTCLK1_M2C_N)* B24(DP9_C2M_P)* B25(DP9_C2M_N)* B28(DP8_C2M_P)* B29(DP8_C2M_N)* B32(DP7_C2M_P)* B33(DP7_C2M_N)* B36(DP6_C2M_P)* B37(DP6_C2M_N)* B40(RES0)* C2(DP0_C2M_P)* C3(DP0_C2M_N)* C10(LA06_P)* C11(LA06_N)* C22(LA18_P_CC)* C23(LA18_N_CC)* C34(GA0)* C35(12P0V)* C37(12P0V)* C39(3P3V)* D1(PG_C2M)* D8(LA01_P_CC)* D9(LA01_N_CC)* D11(LA05_P)* D12(LA05_N)* D13(GND)* D14(LA09_P)* D15(LA09_N)* D17(LA13_P)* D18(LA13_N)* D20(LA17_P_CC)* D21(LA17_N_CC)* D23(LA23_P)* D24(LA23_N)* D26(LA26_P)* D27(LA26_N)* D29(TCK)* D33(TMS)* D34(TRST_N)* D36(3P3V) D38(3P3V) D40(3P3V)* E2(HA01_P_CC)* E3(HA01_N_CC)* E6(HA05_P)* E7(HA05_N)* E9(HA09_P)* E10(HA09_N)* E12(HA13_P)* E13(HA13_N)* E15(HA16_P)* E16(HA16_N)* E18(HA20_P)* E19(HA20_N)* E21(HB03_P)* E22(HB03_N)* E24(HB05_P)* E25(HB05_N)* E27(HB09_P)* E28(HB09_N)* E30(HB13_P)* E31(HB13_N)* E33(HB21_P)* E34(HB21_N)* E36(HB20_P)* E37(HB20_N)* E39(VADJ)* F4(HA00_P_CC)* F5(HA00_N_CC)* F7(HA04_P)* F8(HA04_N)* F10(HA08_P)* F11(HA08_N)* F13(HA12_P)* F14(HA12_N)* F16(HA15_P)* F17(HA15_N)* F19(HA19_P)* F20(HA19_N)* F22(HB02_P)* F23(HB02_N)* F25(HB04_P)* F26(HB04_N)* F28(HB08_P)* F29(HB08_N)* F31(HB12_P)* F32(HB12_N)* F34(HB16_P)* F35(HB16_N)* F37(HB19_P)* F38(HB19_N)* F40(VADJ)* G2(CLK0_C2M_P)* G3(CLK0_C2M_N)* G6(LA00_P_CC)* G7(LA00_N_CC)* G13(LA08_N)* G15(LA12_P)* G16(LA12_N)* G18(LA16_P)* G19(LA16_N)* G22(LA20_N)* G25(LA22_N)* G27(LA25_P)* G28(LA25_N)* G30(LA29_P)* G31(LA29_N)* G37(LA33_N)* G39(VADJ)* H1(VREF_A_M2C)* H2(PRSNT_M2C_N)* H4(CLK0_M2C_P)* H5(CLK0_M2C_N)* H10(LA04_P)* H11(LA04_N)* H13(LA07_P)* H14(LA07_N)* H16(LA11_P)* H17(LA11_N)* H19(LA15_P)* H20(LA15_N)* H22(LA19_P)* H23(LA19_N)* H25(LA21_P)* H26(LA21_N)* H28(LA24_P)* H29(LA24_N)* H32(LA28_N)* H37(LA32_P)* H38(LA32_N)* H40(VADJ)* J2(CLK1_C2M_P)* J3(CLK1_C2M_N)* J6(HA03_P)* J7(HA03_N)* J9(HA07_P)* J10(HA07_N)* J12(HA11_P)* J13(HA11_N)* J15(HA14_P)* J16(HA14_N)* J18(HA18_P)* J19(HA18_N)* J21(HA22_P)* J22(HA22_N)* J24(HB01_P)* J25(HB01_N)* J27(PB07_P)* J28(HB07_N)* J30(HB11_P)* J31(HB11_N)* J33(HB15_P)* J34(HB15_N)* J36(HB18_P)* J37(HB18_N)* J39(VIO_B_M2C)* K1(VREF_B_M2C)* K4(CLK1_M2C_P)* K5(CLK1_M2C_N)* K7(HA02_P)* K8(HA02_N)* K10(HA06_P)* K11(HA06_N)* K14(HA10_N)* K16(HA17_P_CC)* K17(HA17_N_CC)* K19(HA21_P)* K20(HA21_N)* K22(HA23_P)* K23(HA23_N)* K25(HB00_P_CC)* K26(HB00_N_CC)* K28(HB06_P_CC)* K29(HB06_N_CC)* K31(HB10_P)* K32(HB10_N)* K34(HB14_P)* K35(HB14_N)* K37(HB17_P_CC)* K38(HB17_N_CC)* K40(VIO_B_M2C)*; JP1 3*; U1 27(CMLB2_N) 28(CMLB2_P) 33(CMLA2_N) 34(CMLA2_P) 39(DNC)* 40(DNC)*; U2 1(NC)*; U3 27(CMLB2_N) 28(CMLB2_P) 33(CMLA2_N) 34(CMLA2_P) 39(DNC)* 40(DNC)*; U4 4(PG)*; U8 6(NC)*; U9 6(NC)*; U10 2(OUT2-)* 3(OUT2+)* 8(OUT0-)* 9(OUT0+)*; U11 31(TEMP)*; U12 3(!Q)*; U13 2(OUT2-)* 3(OUT2+)* 8(OUT0-) 9(OUT0+); U15 4(PG)*; U16 3(!Q)*

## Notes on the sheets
sheet 1
- 200mA output current
- 200mA output current
- 800mA output current
- The following trace lengths are matched to within 1psec:
     ADC_CLK_1, ADC_CLK_2
- 800mA output current
- The following trace lengths are matched to within 1psec:
     ADC_SYSREF_1, ADC_SYSREF_2
- The following trace lengths are matched to within 20psec:
     ADC_SYNC_1, ADC_SYNC_2
- EEPROM
- The following trace lengths are matched to within 1psec:
     6951_CLK_1, 6951_CLK_2
- WP
- PROG
- The following trace lengths are matched to within 1psec:
     6951_SYNC_1, 6951_SYNC_2
- 800mA output current
- +6V IN
- 1100mA output current
- +3V IN
- GND
- GND
- 1100mA output current
- NOTE: UNLESS OTHERWISE SPECIFIED
- 1. ALL RESISTORS ARE IN OHMS, 0402
- 2. ALL CAPACITORS ARE IN MICROFARADS, 0402.
sheet 2
- LVDS
- LVDS
- CML
- CML
- *
- *
- CML
- CML
- LVDS
- LVDS
- LVDS
- LVDS
- CMOS
- NOTE: UNLESS OTHERWISE SPECIFIED
- 1. ALL RESISTORS ARE IN OHMS, 0402
- 2. ALL CAPACITORS ARE IN MICROFARADS, 0402.
sheet 3
- CML
- LVDS
- CML
- LVDS
- CML
- LVDS
- CML
- LVDS
- LVDS
- LVDS
- NOTE: UNLESS OTHERWISE SPECIFIED
- 1. ALL RESISTORS ARE IN OHMS, 0402
- 2. ALL CAPACITORS ARE IN MICROFARADS, 0402.
